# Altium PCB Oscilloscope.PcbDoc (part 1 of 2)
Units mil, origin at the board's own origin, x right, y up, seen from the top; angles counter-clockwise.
Board outline 3937.5 x 3937.5 mil, 4 copper layers (Layer 1, Layer 2, Layer 3, Layer 4), stack 68.734 mil thick; 84 components, 72 nets, 418 pads, 204 vias.
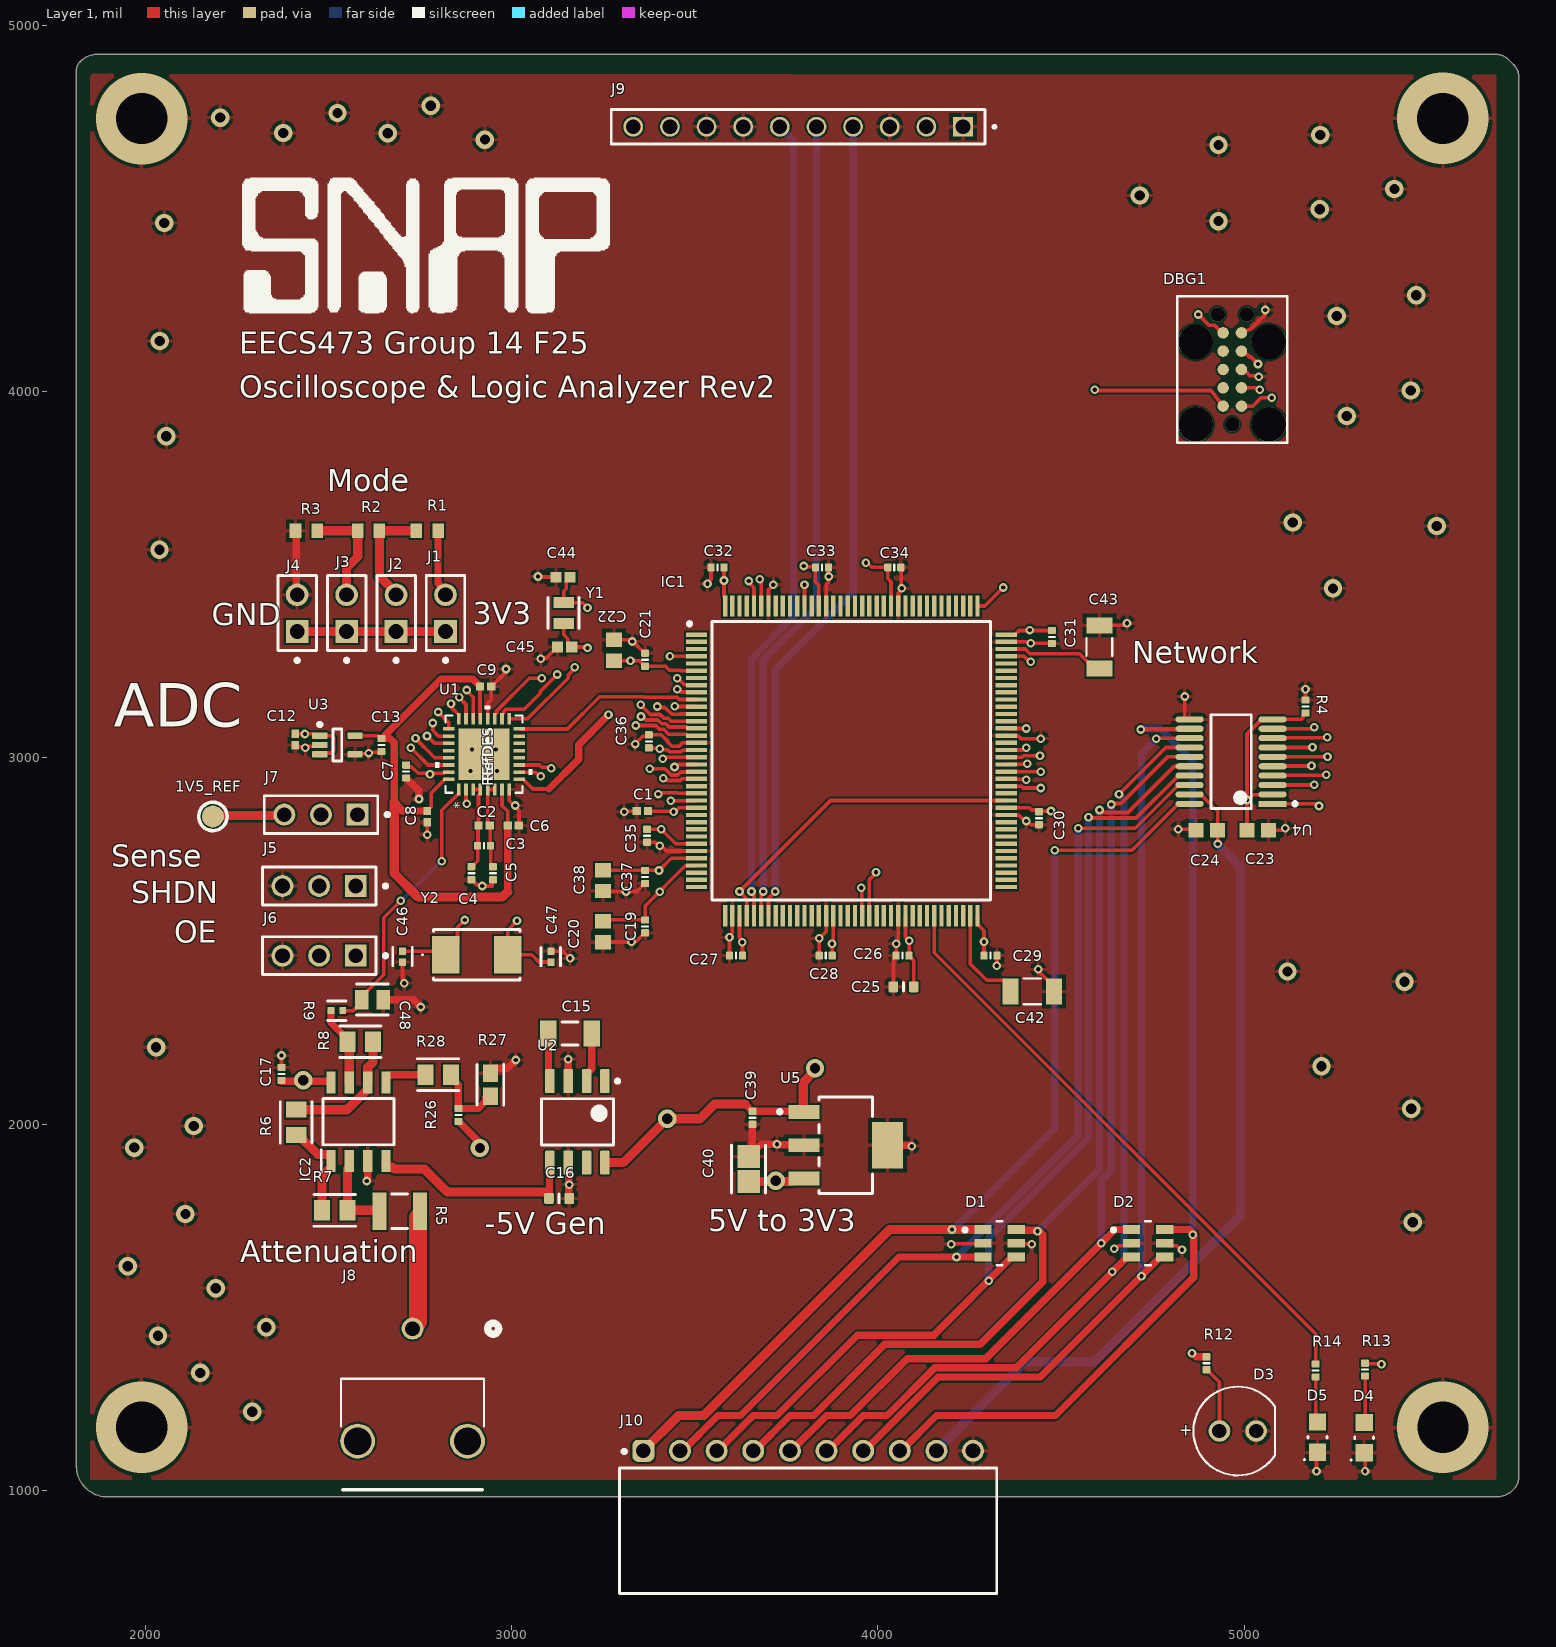
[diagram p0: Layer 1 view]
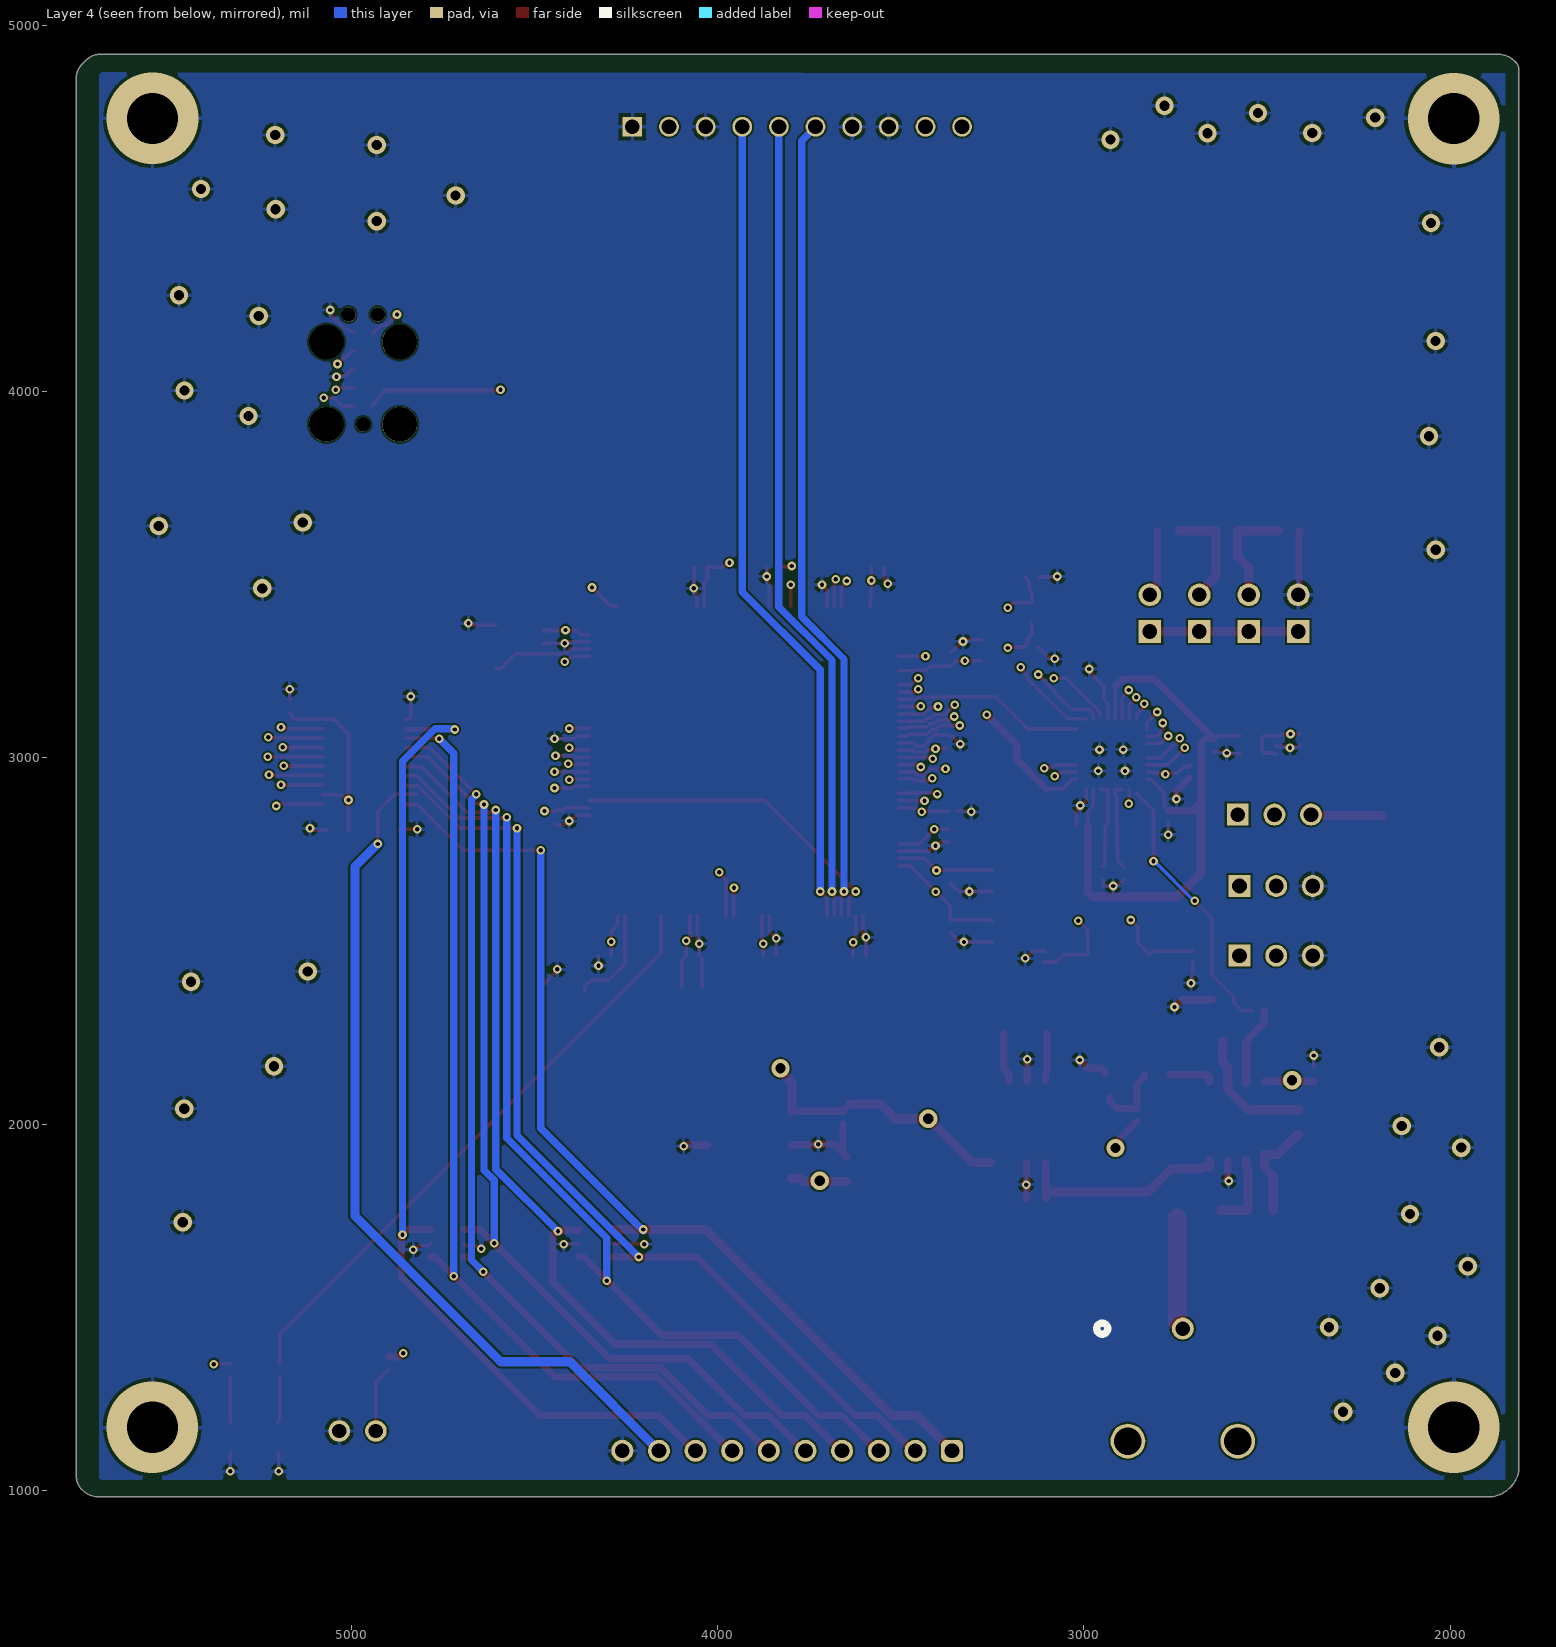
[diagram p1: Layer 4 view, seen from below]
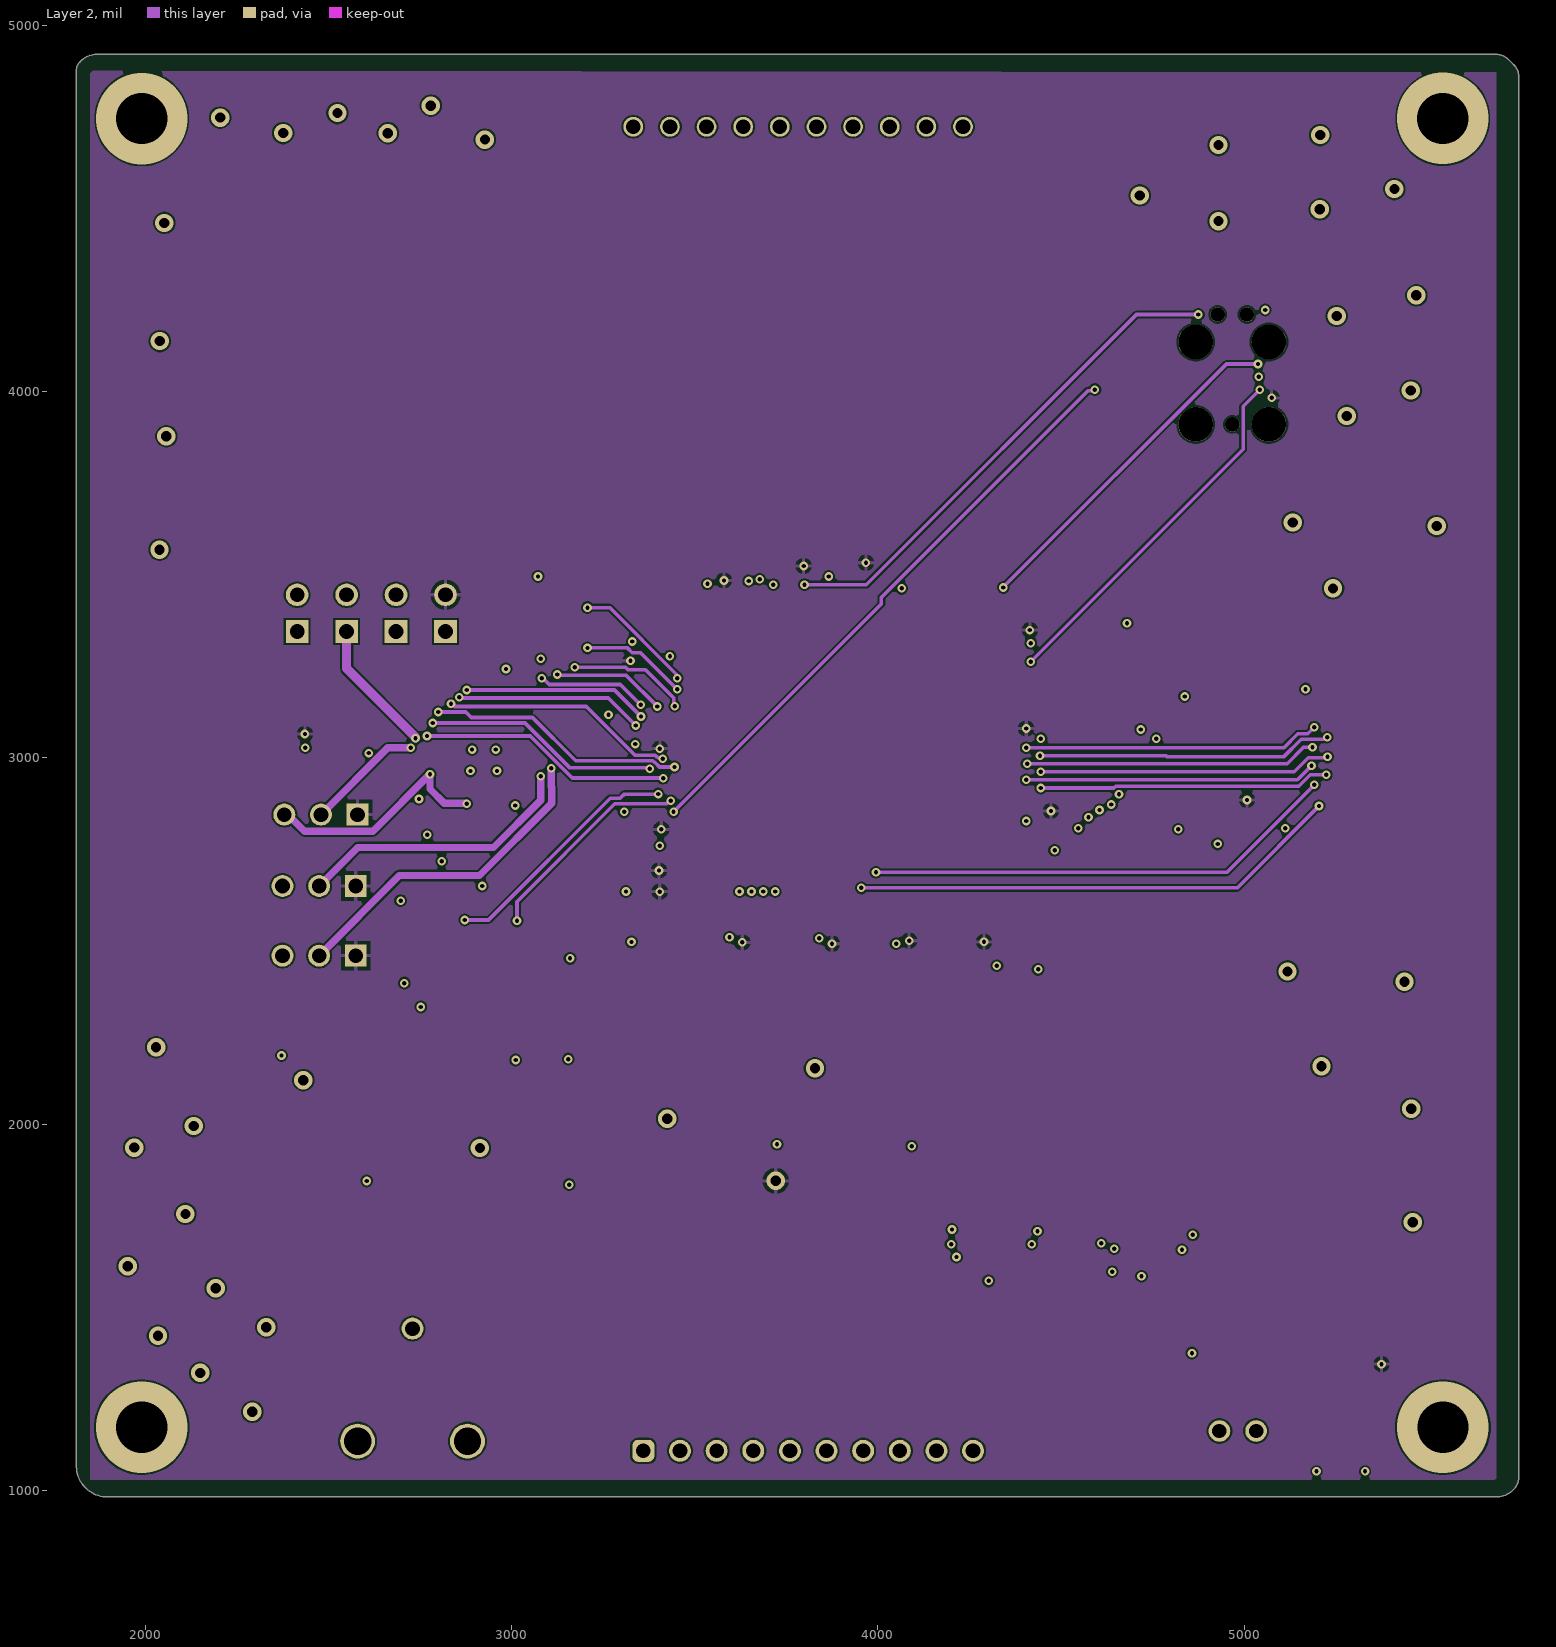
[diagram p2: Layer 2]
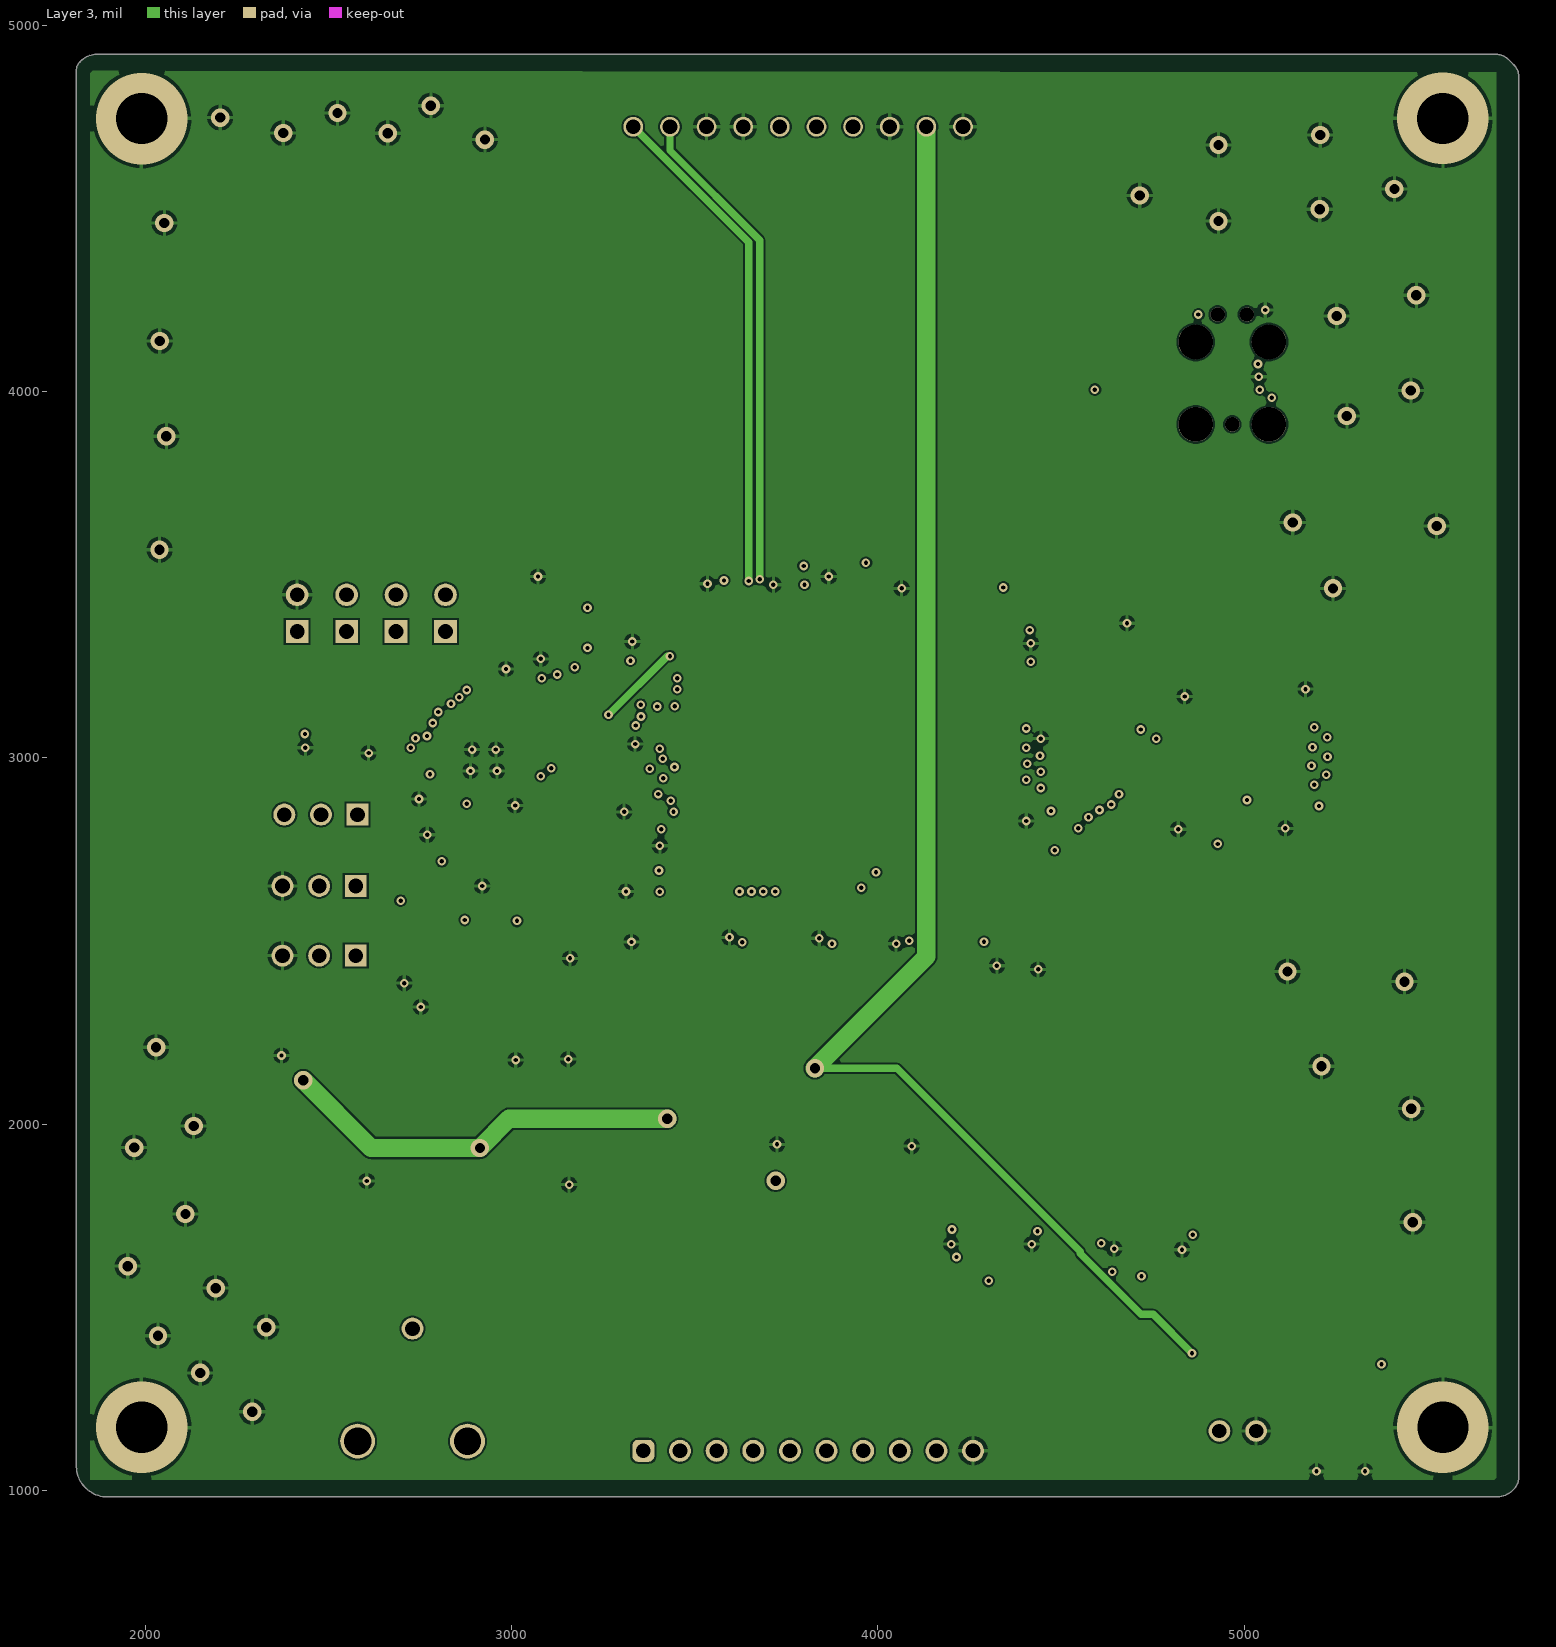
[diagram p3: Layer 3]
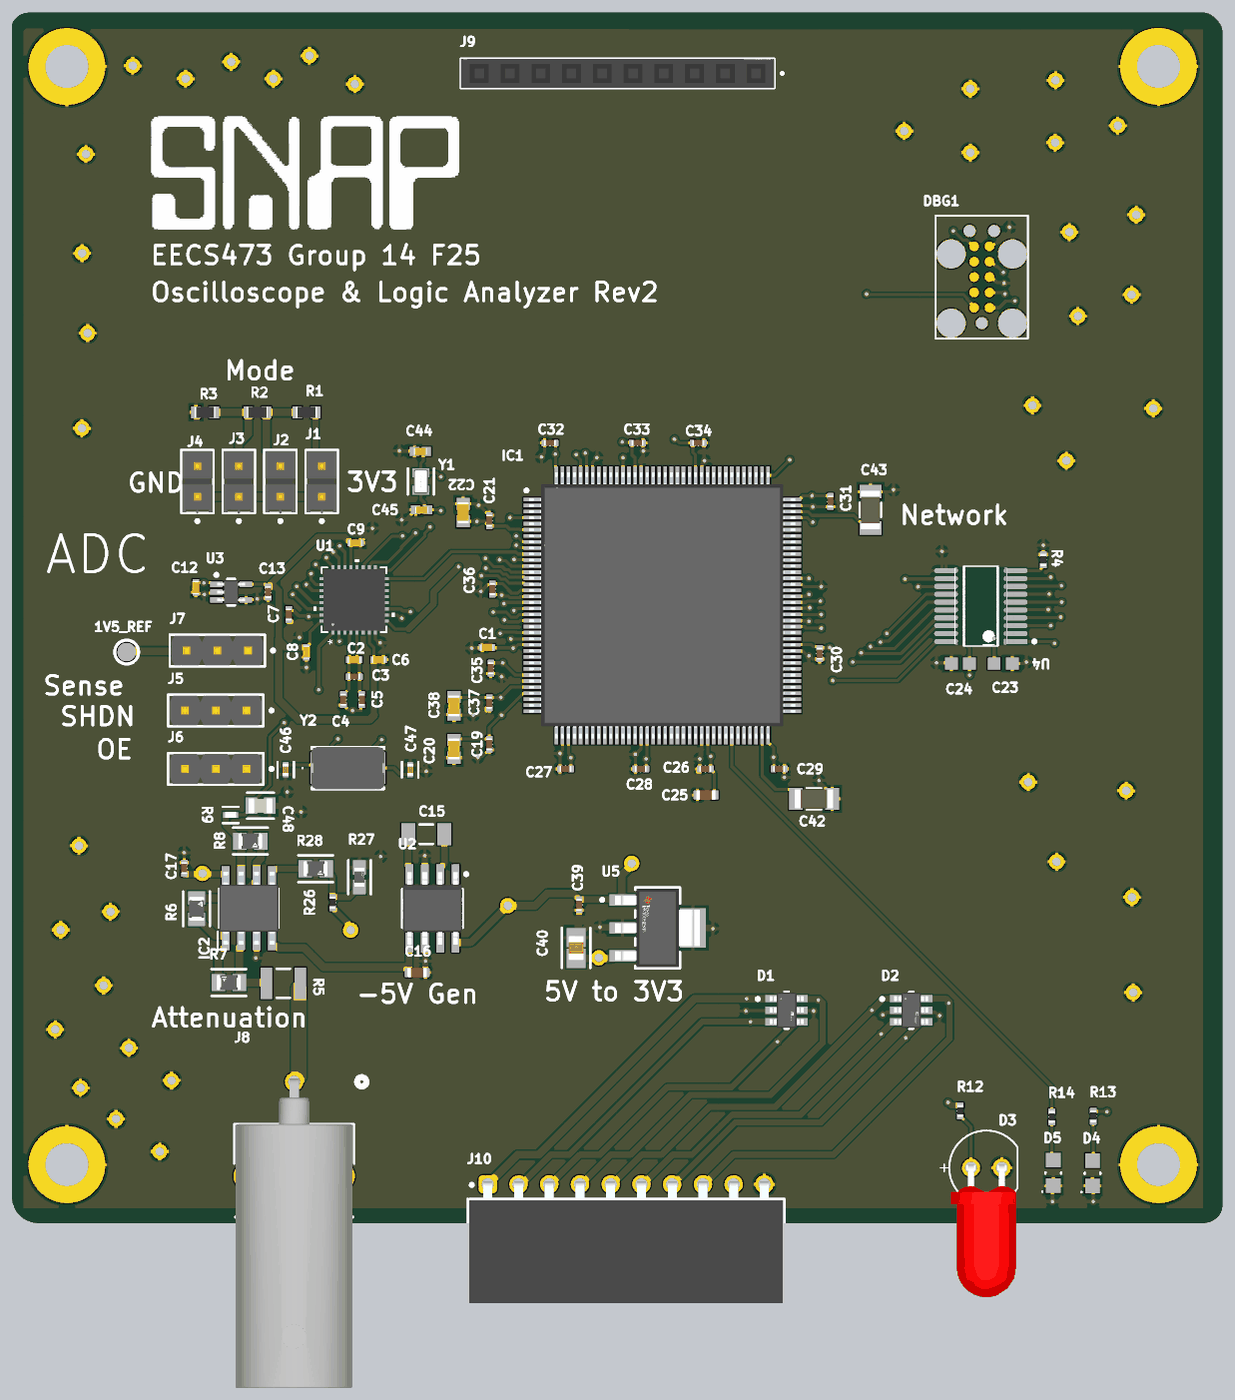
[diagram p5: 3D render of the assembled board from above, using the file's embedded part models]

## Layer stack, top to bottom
Top Solder: solder mask 0.4, Solder Resist, Dk 3.5
Layer 1: signal copper 1.378
Dielectric 2: prepreg 2.8, PP-006, Dk 4.1
Layer 2: signal copper 0.689
Dielectric 1: dielectric 59, FR-4, Dk 4.8
Layer 3: signal copper 0.689
Dielectric 3: prepreg 2.8, PP-006, Dk 4.1
Layer 4: signal copper 1.378
Bottom Solder: solder mask 0.4, Solder Resist, Dk 3.5

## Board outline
1812.5,1064.32 1812.5,4877.5 cw(c1842.68,4877.5) 1821.34,4898.84 1825,4902.5 cw(c1867.25,4860.25) 1867.25,4920 5687.5,4920 cw(c5687.5,4871.72) 5721.64,4905.86 5732.5,4895 5735.86,4891.64 cw(c5701.72,4857.5) 5750,4857.5 5750,1038.71 cw(c5698.79,1038.71) 5735,1002.5 cw(c5686.72,1050.78) 5686.72,982.5 1897.5,982.5 cw(c1897.5,1067) 1837.75,1007.25 1835,1010 cw(c1889.32,1064.32)

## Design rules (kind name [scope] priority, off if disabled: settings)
Clearance [All] p1: gap=5 ignorepadtopadclearanceinfootprint=TRUE
PolygonConnect [All] p1: connectstyle=Relief reliefconductorwidth=10 reliefentries=4 polygonreliefangle="90 Angle" airgapwidth=10
RoutingVias [All] p1: holewidth=28 width=50 viastyle="Through Hole" minholewidth=28 minwidth=50 maxholewidth=28 maxwidth=50
SolderMaskExpansion [All] p1: expansion=4 istentingtop=FALSE
SupplyNets "Schematic Supply Nets_2" [InNet('1V5_ISO')] p1: voltage=0.000
SupplyNets "Schematic Supply Nets_7" [InNet('5V_BUS')] p2: voltage=0.000
SupplyNets "Schematic Supply Nets_5" [InNet('-5V')] p3: voltage=0.000
SupplyNets "Schematic Supply Nets_4" [InNet('1.5V')] p4: voltage=0.000
SupplyNets "Schematic Supply Nets_3" [InNet('GND')] p5: voltage=0.000
SupplyNets "Schematic Supply Nets_1" [InNet('3V3')] p6: voltage=0.000
SupplyNets "Schematic Supply Nets" [InNet('3V3_ADC')] p7: voltage=0.000
Width [All] p1: maxlimit=50 minlimit=10 preferedwidth=10 minimp=50.000000 maximp=50.000000 favimp=50.000000
30 further rules are at their usual default settings.

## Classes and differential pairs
component class micro: C1 C19 C20 C21 C22 C25 C26 C27 C28 C29 C30 C31 C32 C33 C34 C35 C36 C37 C38 C42 C43 C44 C45 C46 C47 D3 D4 D5 DBG1 IC1 R12 R13 R14 Y1 Y2
component class Designator: C23 C24 D1 D2 R4 U4

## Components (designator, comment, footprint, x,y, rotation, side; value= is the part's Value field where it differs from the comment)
1V5_REF "TESTPAD" TESTPAD-Footprint-1 2185,2840 r90 top
C1 "Capacitor 0.1 uF +/- 5% 16 V 0402" CAPC1005X56X25LL10T15 3357.5,2855 r0 top value=100nF
C2 "Capacitor 0.1 uF +/- 5% 16 V 0402" CAPC1005X56X25LL10T15 2925.35,2815 r180 top value=100nF
C3 "Capacitor 2,2µF +/-20% 10V 0402" CAPC0402(1005)60_L 2925.35,2760 r180 top value=2.2µF
C4 "Capacitor 1µF +/-20% 10V 0402" CAPC0402(1005)60_L 2890.35,2685 r270 top value=1µF
C5 "Capacitor 1µF +/-20% 10V 0402" CAPC0402(1005)60_L 2950,2685 r270 top value=1µF
C6 "Capacitor 0.1 uF +/- 5% 16 V 0402" CAPC1005X56X25LL10T15 3005,2815 r180 top value=100nF
C7 "Capacitor 2,2µF +/-20% 10V 0402" CAPC0402(1005)60_L 2712.5,2962.28 r90 top value=2.2µF
C8 "Capacitor 0.1 uF +/- 5% 16 V 0402" CAPC1005X56X25LL10T15 2770,2839.65 r90 top value=100nF
C9 "Capacitor 0.1 uF +/- 5% 16 V 0402" CAPC1005X56X25LL10T15 2929.65,3195 r180 top value=100nF
C12 "Capacitor 0.1 uF +/- 5% 16 V 0402" CAPC1005X56X25LL10T15 2410,3050 r90 top value=100nF
C13 "Capacitor 1µF +/-20% 10V 0402" CAPC0402(1005)60_L 2645,3035 r270 top value=1µF
C15 "47uF" CAPC1206(3216)190_N 3160,2247.5 r0 top
C16 "Capacitor 10µF +/-20% 10V 0603" CAPC0603(1608)100_L 3130,1797.5 r180 top value=10µF
C17 "Capacitor 100nF +/-20% 10V 0402" CAPC0402(1005)60_L 2372.5,2137.28 r90 top value=100nF
C19 "Capacitor 100nF +/-20% 10V 0402" CAPC0402(1005)60_L 3365,2540 r90 top value=100nF
C20 "Capacitor 1uF +/- 10% 16V 0603" CAPC1608X90X35ML15T15 3250,2525 r90 top value=1µF
C21 "Capacitor 100nF +/-20% 10V 0402" CAPC0402(1005)60_L 3365,3267.72 r270 top value=100nF
C22 "Capacitor 1uF +/- 10% 16V 0603" CAPC1608X90X35ML15T15 3280,3293.54 r270 top value=1µF
C23 ".1uF" CAPC1608X90X35NL15T15 5037.03,2802.5 r180 top
C24 ".1uF" CAPC1608X90X35NL15T15 4897.97,2802.5 r0 top
C25 "Capacitor 4.7µF +/-20% 10V 0603" CAPC0603(1608)100_L 4070.16,2375 r0 top value=4.7µF
C26 "Capacitor 100nF +/-20% 10V 0402" CAPC0402(1005)60_L 4067.72,2460 r0 top value=100nF
C27 "Capacitor 100nF +/-20% 10V 0402" CAPC0402(1005)60_L 3612.72,2460 r0 top value=100nF
C28 "Capacitor 100nF +/-20% 10V 0402" CAPC0402(1005)60_L 3857.72,2460 r0 top value=100nF
C29 "Capacitor 100nF +/-20% 10V 0402" CAPC0402(1005)60_L 4307.72,2460 r180 top value=100nF
C30 "Capacitor 100nF +/-20% 10V 0402" CAPC0402(1005)60_L 4440,2835 r90 top value=100nF
C31 "Capacitor 100nF +/-20% 10V 0402" CAPC0402(1005)60_L 4475,3330 r90 top value=100nF
C32 "Capacitor 100nF +/-20% 10V 0402" CAPC0402(1005)60_L 3562.28,3520 r0 top value=100nF
C33 "Capacitor 100nF +/-20% 10V 0402" CAPC0402(1005)60_L 3847.28,3520 r180 top value=100nF
C34 "Capacitor 100nF +/-20% 10V 0402" CAPC0402(1005)60_L 4045,3520 r180 top value=100nF
C35 "Capacitor 100nF +/-20% 10V 0402" CAPC0402(1005)60_L 3370,2787.28 r90 top value=100nF
C36 "Capacitor 100nF +/-20% 10V 0402" CAPC0402(1005)60_L 3375,3045 r270 top value=100nF
C37 "Capacitor 100nF +/-20% 10V 0402" CAPC0402(1005)60_L 3365,2675 r90 top value=100nF
C38 "Capacitor 1uF +/- 10% 16V 0603" CAPC1608X90X35ML15T15 3250,2665 r90 top value=1µF
C39 "Capacitor 470nF +/-40% 10V 0402" CAPC0402(1005)60_L 3657.5,2017.5 r90 top value=470nF
C40 "C2012X5R0J336M125AC" FP-C2012-125-0_2-IPC_A 3647.5,1877.5 r270 top
C42 "0.2uF" CAPC3216X94N 4421.5,2362.5 r180 top
C43 "0.2uF" CAPC3216X94N 4605,3302.5 r270 top
C44 "Capacitor 0.5 pF +/- 0.1pF 25 V 0402" CAPC1005X56X25ML10T15 3140.71,3492.5 r0 top value=0.5pF
C45 "Capacitor 0.5 pF +/- 0.1pF 25 V 0402" CAPC1005X56X25ML10T15 3145,3302.5 r0 top value=0.5pF
C46 "3.9pF" FP-GJM155-0_05-IPC_C 2702.5,2457.5 r270 top
C47 "3.9pF" FP-GJM155-0_05-IPC_C 3107.5,2457.5 r90 top
C48 "C0805C360J1GACTU" FP-C0805C-DN-MFG 2620.47,2340 r0 top value="36 pF"
D1 "ESDA6V1BC6" FP-SOT23-6L-MFG 4332.5,1675 r0 top value=20pF
D2 "ESDA6V1BC6" FP-SOT23-6L-MFG 4737.78,1675 r0 top value=20pF
D3 "151051RS11000" WL-TMRC_D5.9H8.7 4982.5,1162.5 r0 top
D4 "LTST-C170KGKT" LTST-LTST-C170KGKT-2_V 5327.5,1144.37 r90 top
D5 "LTST-C170KGKT" LTST-LTST-C170KGKT-2_V 5200,1145.53 r90 top
DBG1 "TC2050-IDC" TC2050-IDC-Footprint-1 4967.5,4060 r90 top
IC1 "STM32H723ZGT6" QFP50P2200X2200X160-144N 3927.76,2991.73 r0 top
IC2 "LM358DR" SOIC127P600X175-8N 2582.5,2006.77 r90 top
J1 "TSW-102-12-T-S" FP-TSW-102-12-T-S-MFG 2820,3395 r90 top
J2 "TSW-102-12-T-S" FP-TSW-102-12-T-S-MFG 2685,3395 r90 top
J3 "TSW-102-12-T-S" FP-TSW-102-12-T-S-MFG 2550,3395 r90 top
J4 "TSW-102-12-T-S" FP-TSW-102-12-T-S-MFG 2415,3395 r90 top
J5 "MTLW-103-07-G-S-230" FP-MTLW-103-07-G-S-230-MFG 2475,2650 r180 top
J6 "MTLW-103-07-G-S-230" FP-MTLW-103-07-G-S-230-MFG 2475,2460 r180 top
J7 "MTLW-103-07-G-S-230" FP-MTLW-103-07-G-S-230-MFG 2480,2845 r180 top
J8 "731713150" CONN_731713150_MOL 2730,1442 r0 top
J9 "SSQ-110-04-G-S" SAMTEC_SSQ-110-04-G-S 3782.5,4722.5 r180 top
J10 "613010143121" 613010143121 3810,890 r0 top
R1 "Resistor 1k +/-1% 0603 100 mW" RESC1608X55X25ML10T15 2770,3620 r0 top value=1k
R2 "Resistor 1k +/-1% 0603 100 mW" RESC1608X55X25ML10T15 2610,3620 r0 top value=1k
R3 "Resistor 1k +/-1% 0603 100 mW" RESC1608X55X25ML10T15 2440,3620 r0 top value=1k
R4 "Resistor 10K  +/-1 % 0402 63 mW" RESC0402(1005)_L 5167.5,3139.78 r270 top value=10k
R5 "210K 1% 1210(3225)" RESC1210(3225)_L 2695,1762.5 r180 top value="210000.00 Ohm"
R6 "10K5" FP-CRCW0805-HPe3-IPC_B 2412.5,2005 r270 top
R7 "10K5" FP-CRCW0805-HPe3-IPC_B 2517.5,1765 r0 top
R8 "10K5" FP-CRCW0805-HPe3-IPC_B 2587.5,2225 r180 top
R9 "CRCW040220R0FKEE" FP-CRCW0402-e3-IPC_C 2523.33,2310 r0 top
R12 "200R2J" RESC0402(1005)_L 4897.5,1347.28 r270 top value=200
R13 "100R2F" RESC0402(1005)_L 5330,1330 r270 top value=100
R14 "100R2F" RESC0402(1005)_L 5195,1327.72 r270 top value=100
R26 "Resistor 2K2  +/-5 % 0402 63 mW" RESC0402(1005)_L 2855,2025 r90 top value=2.2k
R27 "RMCF0603JT390R" FP-RMCF0603-IPC_A 2942.5,2107.5 r90 top
R28 "10K5" FP-CRCW0805-HPe3-IPC_B 2800,2135 r180 top
U1 "LTC2236CUHPBF" QFN-32_UH_LIT 2925,3010 r90 top
U2 "LM2663MX/NOPB" D0008A_M 3180,2006.28 r270 top
U3 "TLV70033DCKR" DCK0005A_M 2525,3035 r0 top
U4 "TXS0108EPWR" FP-PW0020A-IPC_A 4964.3,2989.7 r180 top
U5 "LM3940IMPX-3.3/NOPB" FP-DCY0004A-MFG 3912.5,1942.5 r0 top
Y1 "ABS06-32.768KHZ-T" FP-ABS06-MFG 3142.5,3395 r270 top
Y2 "ABM7-25.000MHZ-4-T" ABM7 2905,2462.5 r0 top

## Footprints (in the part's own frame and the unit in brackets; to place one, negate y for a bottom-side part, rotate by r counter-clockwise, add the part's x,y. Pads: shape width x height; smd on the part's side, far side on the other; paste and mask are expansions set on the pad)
613010143121 [mm] "Socket Header, Pitch 2.54 mm, THT, Angled, single row, 10p"
  rrect50% 1.52x1.52 hole 1.02: 1(-11.43,5.55)
  round 1.52 hole 1.02: 2(-8.89,5.55) 3(-6.35,5.55) 4(-3.81,5.55) 5(-1.27,5.55) 6(1.27,5.55) 7(3.81,5.55) 8(6.35,5.55) 9(8.89,5.55) 10(11.43,5.55)
  silkscreen extent -13.08,-4.35 13.08,5.62, body extent -12.95,-4.25 12.95,5.75, height 2.55
ABM7 [mm]
  rect 1.9x2.6 smd: 1(-2.15,0) 2(2.15,0)
  silkscreen extent -3.8,-1.75 3,1.75, body extent -3,-1.75 3,1.75, height 1.4
CAPC0402(1005)60_L [mm] "Chip Capacitor, Body 1.0x0.5mm, Height 0.6mm, IPC High Density"
  rrect25% 0.5x0.55 smd: 1(-0.45,0) 2(0.45,0)
  silkscreen extent 0,-0.2 0,0.2, body extent -0.5,-0.25 0.5,0.25, height 0.6
CAPC0603(1608)100_L [mm] "Chip Capacitor, Body 1.6x0.8mm, Height 1.0mm, IPC High Density"
  rrect25% 0.66x0.76 smd: 1(-0.7,0) 2(0.7,0)
  silkscreen extent 0,-0.3 0,0.3, body extent -0.8,-0.4 0.8,0.4, height 0.95
CAPC1005X56X25LL10T15 [mm] "Chip Capacitor, 2-Leads, Body 1.10x0.60mm, IPC High Density"
  rect 0.58x0.54 smd: 1(-0.39,0) 2(0.39,0)
  body extent -0.55,-0.3 0.55,0.3, height 0.56
CAPC1005X56X25ML10T15 [mm] "Chip Capacitor, 2-Leads, Body 1.10x0.60mm, IPC Low Density"
  rect 0.78x0.74 smd: 1(-0.49,0) 2(0.49,0)
  body extent -0.55,-0.3 0.55,0.3, height 0.56
CAPC1206(3216)190_N [mm] "Chip Capacitor, Body 3.2x1.6mm, Height 1.9mm, IPC Medium Density"
  rect 1.15x1.8 smd: 1(-1.5,0) 2(1.5,0)
  silkscreen extent -0.55,-0.8 0.55,0.8, body extent -1.7,-0.9 1.7,0.9, height 1.9
CAPC1608X90X35ML15T15 [mm] "Chip Capacitor, 2-Leads, Body 1.75x0.95mm, IPC Low Density"
  rect 1x1.1 smd: 1(-0.725,0) 2(0.725,0)
  body extent -0.87,-0.48 0.87,0.48, height 0.9
CAPC1608X90X35NL15T15 [mm] "Chip Capacitor, 2-Leads, Body 1.60x0.81mm, IPC Medium Density"
  rect 1.05x1 smd: 1(-0.75,0) 2(0.75,0)
  body extent -0.88,-0.48 0.87,0.48, height 0.9
CAPC3216X94N [mil]
  rect 44x71 smd: 1(-59,0) 2(59,0)
  silkscreen extent -24,-35 24,35, body extent -63,-31 63,31, height 37
CONN_731713150_MOL [mil]
  round 60 hole 40: 1(0,0)
  round 95 hole 75: 2(-150,-307) 3(150,-307)
  silkscreen extent -195,-440 235,15, body extent -190,-996 190,10, height 368
D0008A_M [mm] "SOIC, 8-Leads, Body 5x4mm, Pitch 1.27mm, IPC Low Density"
  rrect15% 1.65x0.65 smd: 1(-2.825,1.905) 2(-2.825,0.635) 3(-2.825,-0.635) 4(-2.825,-1.905) 5(2.825,-1.905) 6(2.825,-0.635) 7(2.825,0.635) 8(2.825,1.905)
  silkscreen extent -2.95,-2.5 1.6,2.91, body extent -3,-2.45 3,2.45, height 1.63
DCK0005A_M [mm] "SOT23, 5-Leads, Body 2.15x1.4mm, Pitch 0.65mm, IPC Low Density"
  rrect22% 1.05x0.45 smd: 1(-1.225,0.65) 2(-1.225,0) 3(-1.225,-0.65) 4(1.225,-0.65) 5(1.225,0.65)
  silkscreen extent -1.35,-1.1 0.3,1.55, body extent -1.14,-1 1.14,1, height 0.94
FP-ABS06-MFG [mm]
  rect 0.75x1.4 smd paste+0 mask+0: 1(-0.725,0) 2(0.725,0)
  silkscreen extent -1.07,-1.07 1.07,1.07, body extent -1.2,-0.8 1.2,0.8, height 0.25
FP-C0805C-DN-MFG [mm]
  rect 0.95x1.35 smd paste+0 mask+0: 1(-0.75,0) 2(0.75,0)
  silkscreen extent -1.1,-1.07 1.1,1.07, body extent -1.4,-0.85 1.4,0.85, height 0.25
FP-C2012-125-0_2-IPC_A [mil]
  rect 62.13x61.27 smd paste+0 mask+0: 1(-34.02,0) 2(34.02,0)
  silkscreen extent -65,-46 65,46, body extent -85,-50 85,50, height 10
FP-CRCW0402-e3-IPC_C [mil]
  rect 18.43x18.6 smd paste+0 mask+0: 1(-15.83,0) 2(15.83,0)
  silkscreen extent -25,-27 25,27, body extent -29,-15 29,15, height 10
FP-CRCW0805-HPe3-IPC_B [mil]
  rect 43.55x55.44 smd paste+0 mask+0: 1(-34.49,0) 2(34.49,0)
  silkscreen extent -56,-43 56,43, body extent -66,-38 66,38, height 10
FP-DCY0004A-MFG [mm]
  rect 2.15x0.95 smd paste+0 mask+0: 1(-2.9,2.3) 2(-2.9,0) 3(-2.9,-2.3)
  rect 2.15x3.25 smd paste+0 mask+0: 4(2.9,0)
  silkscreen extent -4.7,-3.35 1.85,3.35, body extent -4.08,-3.45 4.08,3.45, height 0.25
FP-GJM155-0_05-IPC_C [mil]
  rect 20.29x18.6 smd paste+0 mask+0: 1(-14.9,0) 2(14.9,0)
  silkscreen extent -25,-27 25,27, body extent -29,-15 29,15, height 10
FP-MTLW-103-07-G-S-230-MFG [mm]
  rect 1.52x1.52 hole 1.02 paste-2539.97 mask+0: 1(-2.54,0)
  round 1.52 hole 1.02 paste-2539.97 mask+0: 2(0,0) 3(2.54,0)
  silkscreen extent -4.73,-1.31 3.94,1.31, body extent -4.04,-1.41 4.04,1.41, height 0.25
FP-PW0020A-IPC_A [mm]
  rect 1.955x0.421 smd paste+0 mask+0: 1(-2.875,2.925)
  rrect100% 1.955x0.421 smd paste+0 mask+0: 2(-2.875,2.275) 3(-2.875,1.625) 4(-2.875,0.975) 5(-2.875,0.325) 6(-2.875,-0.325) 7(-2.875,-0.975) 8(-2.875,-1.625) 9(-2.875,-2.275) 10(-2.875,-2.925) 11(2.875,-2.925) 12(2.875,-2.275) 13(2.875,-1.625) 14(2.875,-0.975) 15(2.875,-0.325) 16(2.875,0.325) 17(2.875,0.975) 18(2.875,1.625) 19(2.875,2.275) 20(2.875,2.925)
  silkscreen extent -4.55,-3.25 1.4,3.25, body extent -4.35,-3.75 4.35,3.75, height 0.25
FP-RMCF0603-IPC_A [mil]
  rect 47.48x41.66 smd paste+0 mask+0: 1(-31.54,0) 2(31.54,0)
  silkscreen extent -55,-37 55,37, body extent -75,-41 75,41, height 10
FP-SOT23-6L-MFG [mm]
  rect 1.2x0.6 smd paste+0 mask+0: 1(-1.15,0.95) 2(-1.15,0) 3(-1.15,-0.95) 4(1.15,-0.95) 5(1.15,0) 6(1.15,0.95)
  silkscreen extent -2.52,-1.53 0.18,1.53, body extent -1.85,-1.63 1.85,1.63, height 0.25
FP-TSW-102-12-T-S-MFG [mm]
  rect 1.57x1.57 hole 1.02 paste-2539.97 mask+0: 1(-1.27,0)
  round 1.57 hole 1.02 paste-2539.97 mask+0: 2(1.27,0)
  silkscreen extent -3.4,-1.34 2.61,1.34, body extent -2.71,-1.44 2.71,1.44, height 0.25
LTST-LTST-C170KGKT-2_V [mm] "SMD, 2-Leads, Body 2.00x1.25mm"
  rect 1.2x1.2 smd: 1(-1.05,0) 2(1.05,0)
  silkscreen extent -1.6,-0.65 0.05,0.95, body extent -1,-0.63 1,0.63, height 1.1
QFN-32_UH_LIT [mm]
  rect 0.805x0.249 smd paste+0 mask+0: 1(-2.452,1.75) 2(-2.452,1.25) 3(-2.452,0.75) 4(-2.452,0.25) 5(-2.452,-0.25) 6(-2.452,-0.75) 7(-2.452,-1.25) 8(-2.452,-1.75) 17(2.452,-1.75) 18(2.452,-1.25) 19(2.452,-0.75) 20(2.452,-0.25) 21(2.452,0.25) 22(2.452,0.75) 23(2.452,1.25) 24(2.452,1.75)
  rect 0.249x0.805 smd paste+0 mask+0: 9(-1.75,-2.452) 10(-1.25,-2.452) 11(-0.75,-2.452) 12(-0.25,-2.452) 13(0.25,-2.452) 14(0.75,-2.452) 15(1.25,-2.452) 16(1.75,-2.452) 25(1.75,2.452) 26(1.25,2.452) 27(0.75,2.452) 28(0.25,2.452) 29(-0.25,2.452) 30(-0.75,2.452) 31(-1.25,2.452) 32(-1.75,2.452)
  rect 3.55x3.55 smd paste-1.775 mask+0: 33(0,0)
  silkscreen extent -2.68,-3.36 3.36,3.36, body extent -2.55,-2.55 2.55,2.55, height 0.8
QFP50P2200X2200X160-144N [mm]
  rect 1.475x0.3 smd: 1(-10.738,8.75) 2(-10.738,8.25) 3(-10.738,7.75) 4(-10.738,7.25) 5(-10.738,6.75) 6(-10.738,6.25) 7(-10.738,5.75) 8(-10.738,5.25) 9(-10.738,4.75) 10(-10.738,4.25) 11(-10.738,3.75) 12(-10.738,3.25) 13(-10.738,2.75) 14(-10.738,2.25) 15(-10.738,1.75) 16(-10.738,1.25) 17(-10.738,0.75) 18(-10.738,0.25) 19(-10.738,-0.25) 20(-10.738,-0.75) 21(-10.738,-1.25) 22(-10.738,-1.75) 23(-10.738,-2.25) 24(-10.738,-2.75) 25(-10.738,-3.25) 26(-10.738,-3.75) 27(-10.738,-4.25) 28(-10.738,-4.75) 29(-10.738,-5.25) 30(-10.738,-5.75) 31(-10.738,-6.25) 32(-10.738,-6.75) 33(-10.738,-7.25) 34(-10.738,-7.75) 35(-10.738,-8.25) 36(-10.738,-8.75) 73(10.738,-8.75) 74(10.738,-8.25) 75(10.738,-7.75) 76(10.738,-7.25) 77(10.738,-6.75) 78(10.738,-6.25) 79(10.738,-5.75) 80(10.738,-5.25) 81(10.738,-4.75) 82(10.738,-4.25) 83(10.738,-3.75) 84(10.738,-3.25) 85(10.738,-2.75) 86(10.738,-2.25) 87(10.738,-1.75) 88(10.738,-1.25) 89(10.738,-0.75) 90(10.738,-0.25) 91(10.738,0.25) 92(10.738,0.75) 93(10.738,1.25) 94(10.738,1.75) 95(10.738,2.25) 96(10.738,2.75) 97(10.738,3.25) 98(10.738,3.75) 99(10.738,4.25) 100(10.738,4.75) 101(10.738,5.25) 102(10.738,5.75) 103(10.738,6.25) 104(10.738,6.75) 105(10.738,7.25) 106(10.738,7.75) 107(10.738,8.25) 108(10.738,8.75)
  rect 0.3x1.475 smd: 37(-8.75,-10.738) 38(-8.25,-10.738) 39(-7.75,-10.738) 40(-7.25,-10.738) 41(-6.75,-10.738) 42(-6.25,-10.738) 43(-5.75,-10.738) 44(-5.25,-10.738) 45(-4.75,-10.738) 46(-4.25,-10.738) 47(-3.75,-10.738) 48(-3.25,-10.738) 49(-2.75,-10.738) 50(-2.25,-10.738) 51(-1.75,-10.738) 52(-1.25,-10.738) 53(-0.75,-10.738) 54(-0.25,-10.738) 55(0.25,-10.738) 56(0.75,-10.738) 57(1.25,-10.738) 58(1.75,-10.738) 59(2.25,-10.738) 60(2.75,-10.738) 61(3.25,-10.738) 62(3.75,-10.738) 63(4.25,-10.738) 64(4.75,-10.738) 65(5.25,-10.738) 66(5.75,-10.738) 67(6.25,-10.738) 68(6.75,-10.738) 69(7.25,-10.738) 70(7.75,-10.738) 71(8.25,-10.738) 72(8.75,-10.738) 109(8.75,10.738) 110(8.25,10.738) 111(7.75,10.738) 112(7.25,10.738) 113(6.75,10.738) 114(6.25,10.738) 115(5.75,10.738) 116(5.25,10.738) 117(4.75,10.738) 118(4.25,10.738) 119(3.75,10.738) 120(3.25,10.738) 121(2.75,10.738) 122(2.25,10.738) 123(1.75,10.738) 124(1.25,10.738) 125(0.75,10.738) 126(0.25,10.738) 127(-0.25,10.738) 128(-0.75,10.738) 129(-1.25,10.738) 130(-1.75,10.738) 131(-2.25,10.738) 132(-2.75,10.738) 133(-3.25,10.738) 134(-3.75,10.738) 135(-4.25,10.738) 136(-4.75,10.738) 137(-5.25,10.738) 138(-5.75,10.738) 139(-6.25,10.738) 140(-6.75,10.738) 141(-7.25,10.738) 142(-7.75,10.738) 143(-8.25,10.738) 144(-8.75,10.738)
  silkscreen extent -11.35,-9.65 9.65,9.65, body extent -11,-11 11,11, height 1.6
RESC0402(1005)_L [mm] "Chip Resistor, Body 1.0x0.5mm, IPC High Density"
  rrect25% 0.5x0.55 smd: 1(-0.45,0) 2(0.45,0)
  silkscreen extent 0,-0.2 0,0.2, body extent -0.5,-0.25 0.5,0.25, height 0.3
RESC1210(3225)_L [mm] "Chip Resistor, Body 3.2x2.5mm, IPC High Density"
  rect 0.95x2.6 smd: 1(-1.4,0) 2(1.4,0)
  silkscreen extent -0.55,-1.2 0.55,1.2, body extent -1.7,-1.35 1.7,1.35, height 0.71
RESC1608X55X25ML10T15 [mm] "Chip Resistor, 2-Leads, Body 1.70x0.90mm, IPC Low Density"
  rect 0.8x1 smd: 1(-0.75,0) 2(0.75,0)
  body extent -0.85,-0.45 0.85,0.45, height 0.55
SAMTEC_SSQ-110-04-G-S [mm]
  rect 1.37x1.37 / inner round 1.37 / far side rect 1.37x1.37 hole 1.02: 01(-11.43,0)
  round 1.37 hole 1.02: 02(-8.89,0) 03(-6.35,0) 04(-3.81,0) 05(-1.27,0) 06(1.27,0) 07(3.81,0) 08(6.35,0) 09(8.89,0) 10(11.43,0)
  silkscreen extent -13.7,-1.2 12.96,1.2, body extent -12.95,-1.21 12.95,1.21, height 8.51
SOIC127P600X175-8N [mm]
  rect 1.525x0.65 smd: 1(-2.712,1.905) 2(-2.712,0.635) 3(-2.712,-0.635) 4(-2.712,-1.905) 5(2.712,-1.905) 6(2.712,-0.635) 7(2.712,0.635) 8(2.712,1.905)
  silkscreen extent -3.47,-2.45 1.6,2.58, body extent -3,-2.45 3,2.45, height 1.75
TC2050-IDC-Footprint-1 [mm]
  round 0.8 smd paste-0.9: 1(-2.54,-0.635) 2(-1.27,-0.635) 3(0,-0.635) 4(1.27,-0.635) 5(2.54,-0.635) 6(2.54,0.635) 7(1.27,0.635) 8(0,0.635) 9(-1.27,0.635) 10(-2.54,0.635)
  round 1 hole 1 paste-2539.97: A(-3.81,0) B(3.81,-1.016) C(3.81,1.016)
  round 2.4 hole 2.4 paste-2539.97: D(-3.81,-2.54) E(1.905,-2.54) F(1.905,2.54) G(-3.81,2.54)
  silkscreen extent -5.08,-3.81 5.08,3.81
TESTPAD-Footprint-1 [mil]
  round 60 smd: PAD(0,0)
  silkscreen extent -39,-39 39,39
WL-TMRC_D5.9H8.7 [mm] "THT Mono-color Round Color LED, 2-leads"
  round 1.5 hole 1: 1(-1.27,0) 2(1.27,0)
  silkscreen extent -3.07,-3.07 2.58,3.08, body extent -2.95,-10.7 2.45,0.25, height 5.95

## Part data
1V5_REF: library part CMP-002-00073-1, "PCB TESTPAD"
C1 C2 C6 C8 C9 C12: library part CMP-001-00001-6, "Chip Capacitor, 0.1 uF, +/- 5%, 16 V, 0402 (1005 Metric)", Capacitor Type=Ceramic, Case/Package=0402, Max Operating Temperature=125°C, Min Operating Temperature=-55°C, Tolerance=5%, Voltage Rating=16V
C3 C7: library part CMP-001-00056-4, "Chip Capacitor, 2,2µF +/-20%, 10V, 0402, Thickness 0.6 mm", Case/Package=0402, Max Operating Temperature=85°C, Min Operating Temperature=-55°C, Tolerance=10%, Voltage Rating=10V
C4 C5 C13: library part CMP-001-00063-3, "Chip Capacitor, 1µF +/-20%, 10V, 0402, Thickness 0.6 mm", Case/Package=0402, Max Operating Temperature=85°C, Min Operating Temperature=-55°C, Tolerance=10%, Voltage Rating=10V
C15: library part CMP-1037-05002-1, "CAP 47uF 10V ±20% 1206 (3216 Metric) Thickness 1.9mm SMD", Case-EIA=1206, Case-Metric=3216, Rated Voltage="10 V", Tolerance=Â±20%
C16: library part CMP-001-00075-4, "Chip Capacitor, 10µF +/-20%, 10V, 0603, Thickness 1 mm", Case/Package=0603, Max Operating Temperature=85°C, Min Operating Temperature=-55°C, Tolerance=10%, Voltage Rating=10V
C17 C19 C21 C26 C27 C28 C29 C30 C31 C32 C33 C34 C35 C36 C37: library part CMP-001-00061-3, "Chip Capacitor, 100nF +/-20%, 10V, 0402, Thickness 0.6 mm", Case/Package=0402, Max Operating Temperature=85°C, Min Operating Temperature=-55°C, Tolerance=20%, Voltage Rating=10V
C20 C22 C38: library part CMP-001-00004-6, "Chip Capacitor, 1 uF, +/- 10%, 16 V, 0603 (1608 Metric)", Capacitor Type=Ceramic, Case/Package=0603, Max Operating Temperature=125°C, Min Operating Temperature=-55°C, Tolerance=10%, Voltage Rating=16V
C23 C24: library part CMP-2006-02299-1, "C0603C104K4RAC7013", Manufacturer=Kemet
C25: library part CMP-001-00076-4, "Chip Capacitor, 4.7µF +/-20%, 10V, 0603, Thickness 1 mm", Case/Package=0603, Max Operating Temperature=85°C, Min Operating Temperature=-55°C, Tolerance=10%, Voltage Rating=10V
C39: library part CMP-001-00060-4, "Chip Capacitor, 470nF +/-40%, 10V, 0402, Thickness 0.6 mm", Case/Package=0402, Max Operating Temperature=85°C, Min Operating Temperature=-55°C, Tolerance=20%, Voltage Rating=10V
C40: library part CMP-08246-003796-1, "Multilayer Ceramic Capacitors 33μF ±20% 6.3V X5R SMD 0805", Capacitance=33uF, Case Code (Imperial)=0805, Case Code (Metric)=2012, Dielectric=X5R, Dielectric Material=Ceramic, Max Operating Temperature=85°C, Min Operating Temperature=-55°C, Package Quantity=1, Tolerance=20%, Voltage Rating=6.3V
C42 C43: library part 12063C204KAT4A, "Capacitor", Manufacturer_Name="Kyocera AVX", Mouser Part Number=581-12063C204KAT4A
C44 C45: library part CMP-001-00002-6, "Chip Capacitor, 0.5 pF, +/- 0.1pF, 25 V, 0402 (1005 Metric)", Capacitor Type=Ceramic, Case/Package=0402, Max Operating Temperature=125°C, Min Operating Temperature=-55°C, Tolerance=20%, Voltage Rating=25V
C46 C47: library part CMP-2008-03853-2, "Multi-Layer Ceramic Capacitor 3.9pF C0G  ±0.25pF 0402 Paper T/R", Case Code (Imperial)=0402, Case Code (Metric)=1005, Dielectric=C0G, Max Operating Temperature=125°C, Min Operating Temperature=-55°C, Package Quantity=1, Voltage=50V
C48: library part CMP-1036-01479-3, "Capacitor, Ceramic, 36pF, 100VDC, 5-% Tol, 5+% Tol, C0G-TC Code, -30, 30ppm-TC", Capacitance="36 pF", Manufacturer=KEMET, Package=C0805C-DN, Temperature="-55°C to +125°C", Temperature Characteristic=C0G, Temperature Coefficient=30ppm/°C, Temperature Range High=+125°C, Temperature Range Low=-55°C, Tolerance=0.05, Voltage Rating="100 V"
D1 D2: library part CMP-12225-000005-1, "TVS DIODE 5V SOT23-6", Breakdown Voltage=6.1V, Capacitance=20pF, Manufacturer=STMicroelectronics, Max Junction Temp=+150°C, Package=SOT23-6L, Peak Pulse Current=3A, Peak Pulse Power=80W, Reverse Standoff Voltage=5V, Temperature="-40°C to +125°C", Temperature Range High=+125°C, Temperature Range Low=-40°C
D3: library part CMP-007-00039-1, "WL-TMRC Red Color Diffused 5 mm Round Through Hole LED", Case/Package=Radial, Forward Current=100mA, Forward Voltage=2.1V, Max Operating Temperature=85°C, Min Operating Temperature=-40°C
D4 D5: library part CMP-2000-06620-1, "Ultra Bright AlInGaP Chip LED, 75 mW, -55 to 85 degC, 2-Pin SMD (0805), RoHS, Tape and Reel", Emitting Color=YellowGreen, Forward Current=30mA, Forward Voltage=2.4V, Manufacturer=Lite-On, Operating Temp Range=-55Cto85C, Operating Temperature Classification=Industrial, Package Description="2-Pin Surface Mounted Device, Body 2 x 1.25 mm", Package Reference=LTST-C170KGKT-2, Package Type=ChipLed, Power Dissipation=75W, Power Dissipation Max=75mW, Reverse Voltage=5V, Test Current (It)=20mA
DBG1: library part CMP-002-00071-4, "CBL PLUG-OF-NAILS 10-PIN W/LEGS"
IC1: "Integrated Circuit", Manufacturer_Name=STMicroelectronics, Mouser Part Number=511-STM32H723ZGT6
IC2: "Integrated Circuit", Manufacturer_Name="Texas Instruments", Mouser Part Number=595-LM358DR
J1 J2 J3 J4: library part CMP-02766-001444-1, "CONN HEADER VERT 2POS 2.54MM"
J5 J6 J7: library part CMP-02766-001679-1, "CONN HEADER VERT 3POS 2.54MM", Housing Color=Black, Max Current Rating=3A, Max Operating Temperature=125°C, Min Operating Temperature=-55°C
J8: library part CMP-002-00084-4, "JACK, BNC, 50OHM, R/A, THT; Connector Type: BNC Coaxial; Body Style: Right Angle J", Case/Package=None
J9: library part CMP-039-000000-3, "Samtec Connector .1\" pitch, long ahh pins", Package=None
J10: library part CMP-1502-01419-3, Color=Black, Contact Resistance=20mΩ, Current Rating=3A, Flammability Rating="UL94 V-0", Insulation Resistance=1GΩ, Max Operating Temperature=125°C, Min Operating Temperature=-40°C, Operating Supply Voltage=250V
R1 R2 R3: library part CMP-009-00014-5, "Chip Resistor, 1 KOhm, +/-1%, 0.1 W, -55 to 155 degC, 0603 (1608 Metric)", Case/Package=0603, Max Operating Temperature=155°C, Min Operating Temperature=-55°C, Power=100mW, Tolerance=1%, Voltage Rating=50V
R4: library part CMP-009-00149-3, "Chip Resistor, 10 kOhms, +/-1 %, 63 mW, -55 to 125 degC, 0402", Case/Package=0402, Max Operating Temperature=155°C, Min Operating Temperature=-55°C, Power=63mW, Tolerance=1%
R5: library part CMP-1015-00770-1, "210K 0.5W 1% 1210 (3225 Metric)  SMD", Case-EIA=1210, Case-Metric=3225, Power="0.5 W", Tolerance="1 %"
R6 R7 R8 R28: library part CMP-02407-008889-1, "RES Thick Film, 10.5kΩ, 1%, 0.5W, 100ppm/°C, 0805", Case/Package=0805, Max Power Dissipation=333mW, Package Quantity=5000, Resistance=10.5kR, Temperature Coefficient=100ppm/°C, Tolerance=1%
R9: library part CMP-02407-010876-1, "RES Thick Film, 20Ω, 1%, 0.063W, 100ppm/°C, 0402", Case/Package=0402, Max Operating Temperature=155°C, Max Power Dissipation=63mW, Min Operating Temperature=-55°C, Package Quantity=50000, Resistance=20R, Temperature Coefficient=100ppm/°C, Tolerance=1%
R12: library part CMP-009-00079-2, "200R 0.063W 5% 0402 (1005 Metric)  SMD", Case/Package=0402, Power=63mW, Tolerance=5%
R13 R14: library part CMP-009-00065-2, "100R 0.063W 1% 0402 (1005 Metric)  SMD", Case/Package=0402, Power=63mW, Tolerance=1%
R26: library part CMP-009-00166-3, "Chip Resistor, 2,2 kOhms, +/-5 %, 63 mW, -55 to 155 degC, 0402", Case/Package=0402, Max Operating Temperature=155°C, Min Operating Temperature=-55°C, Power=63mW, Tolerance=5%
R27: library part CMP-26527-007258-1, "390Ω ±5% 0.1W 0603 Thick Film Chip Resistor AEC-Q200 compliant", Case Code (Imperial)=0603, Case Code (Metric)=1608, Max Operating Temperature=155°C, Max Power Dissipation=100mW, Min Operating Temperature=-55°C, Resistance=390R, Resistor Type="Thick Film", Temperature Coefficient=200ppm/°C, Tolerance=5%
U1: library part CMP-027-000001-1, "10-Bit, 25Msps Low Noise 3V ADCs", Manufacturer_Name="Analog Devices Inc", Manufacturer_Part_Number=LTC2236CUH#PBF
U2: library part CMP-0065-00039-3, "Switched Capacitor Voltage Converter, 8-pin Narrow SOIC, Pb-Free", Manufacturer="Texas Instruments", PackageTopMarking=NSZXTT*LM26*63M, PowerWise=N
U3: library part CMP-0394-00820-2, "Single Output LDO, 200 mA, Fixed 3.3 V Output, 2 to 5.5 V Input, with Low IQ, 5-pin SC70 (DCK), -40 to 125 degC, Green (RoHS & no Sb/Br)", Manufacturer="Texas Instruments"
U4: library part CMP-016-00012-1, "Eight-bit bidirectional voltage-level shifter for open-drain and push-pull applications 20-TSSOP -40 to 85", Case/Package=TSSOP, Max Operating Temperature=85°C, Max Supply Voltage=5.5V, Min Operating Temperature=-40°C, Min Supply Voltage=1.4V, Nominal Supply Current=3µA
U5: library part CMP-04917-000180-1, "IC REG LINEAR 3.3V 1A SOT223-4", Case/Package=SOT-223, Dropout Voltage=500mV, Max Input Voltage=7.5V, Max Operating Temperature=125°C, Max Output Current=1A, Min Input Voltage=4.5V, Min Operating Temperature=-40°C, Output Voltage=3.3V, Package Quantity=2000, Quiescent Current=15mA
Y1: library part CMP-2000-05035-2, "Crystal 32.768kHz ±20ppm (Tol) 12.5pF FUND 90kΩ 2-Pin Mini-CSMD T/R", Case/Package=CSMD, ESR (Equivalent Series Resistance)=90kR, Frequency=32.768kHz, Frequency Stability=20ppm, Insulation Resistance=500MR, Load Capacitance=12.5pF, Max Operating Temperature=85°C, Min Operating Temperature=-40°C, Operating Frequency="32.768 kHz", Package Quantity=3000
Y2: "Crystal or Oscillator", Manufacturer_Name=ABRACON, Mouser Part Number=815-ABM725000MHZ4T

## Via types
v1: diameter 23.62, hole 11.81, Layer 1 to Layer 4, tented top, 157 vias
v2: diameter 50, hole 28, Layer 1 to Layer 4, 43 vias
v3: diameter 250, hole 140, Layer 1 to Layer 4, 4 vias

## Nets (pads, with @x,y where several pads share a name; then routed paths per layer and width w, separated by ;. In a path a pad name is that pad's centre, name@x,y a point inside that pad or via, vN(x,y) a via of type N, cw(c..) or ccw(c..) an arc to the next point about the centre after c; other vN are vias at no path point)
1.5V: 1V5_REF.PAD C7.2 J7.3 U1.2 U1.31 | length 1004.3
  Layer 1 w10: C7.2@2707.5,2980 2712.34,2975.16 2727.78,2975.16 2745.22,2957.72 2777.5,2957.72 2814.63,2957.72 2817.7,2960.79 U1.31@2828.45,2960.79 ; U1.2@2875.79,2913.45 2875.88,2913.35 2875.88,2876.62 v1(2877.5,2875)
  Layer 1 w25: 1V5_REF.PAD@2185,2840 2187.5,2842.5 2377.5,2842.5 J7.3@2380,2845
  Layer 2 w20: J7.3@2380,2845 2390,2845 2435,2800 2622.03,2800 v1@2776.81,2954.78 ; v1(2777.5,2955.47) 2777.5,2915 2816.81,2875.69 2876.81,2875.69 v1(2877.5,2875)
1V5_ISO: IC2.5 R28.2 | length 127
  Layer 1 w20: IC2.5@2657.5,2113.54 2657.5,2130.77 2660.3,2133.56 2670.57,2133.56 2672.01,2135 R28.2@2765.51,2135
